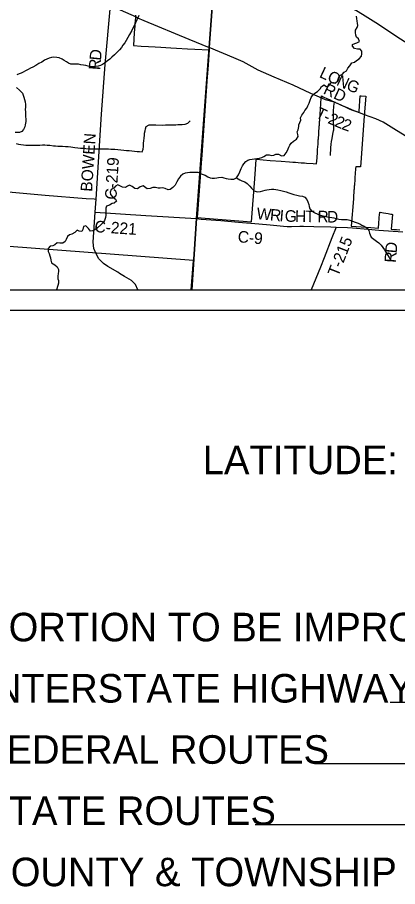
# Model space of a CAD drawing. Extents: x 0 to 34, y 0 to 22.
# Drawn here: x 2.162 to 4.027, y 11.175 to 15.435 of the extents above; entities that cross this region are included whole.
import ezdxf

# ---------------------------------------------------------------- set-up
doc = ezdxf.new("R2010")
doc.units = 0
for name, color, linetype in [('GM_X_Corporation', 7, 'Continuous'), ('GM_X_County', 7, 'Continuous'), ('GM_X_County_Road', 7, 'Continuous'), ('GM_X_County_Road_Text', 7, 'Continuous'), ('GM_X_Minor_River', 7, 'Continuous'), ('GM_X_Rail_Line', 7, 'Continuous'), ('GM_X_Township_Road', 7, 'Continuous'), ('GM_X_Township_Road_Text', 7, 'Continuous'), ('SH_Data', 7, 'Continuous'), ('SH_Text', 7, 'Continuous')]:
    doc.layers.add(name, color=color, linetype=linetype)

msp = doc.modelspace()

# ---------------------------------------------------------------- linework, layer by layer
at = {"layer": 'GM_X_Corporation'}
for points in [[(4.3071, 20.9), (2.1, 20.9), (2.1, 14.1), (3.0169, 14.1), (3.0406, 14.4484), (3.1026, 15.287), (3.1745, 16.2606), (2.934, 16.2765), (2.366, 16.3159), (2.2862, 16.3208), (2.1768, 16.323), (2.2478, 17.3472), (2.3155, 18.3567), (3.8153, 18.2543), (3.8503, 18.7566), (3.8611, 18.9124), (3.8924, 19.3621), (3.9019, 19.4987), (3.9133, 19.6628), (3.9816, 20.645), (3.9912, 20.7822), (4.2975, 20.7549)], [(2.1, 16.3272), (2.1, 14.1), (3.0167, 14.1), (3.0404, 14.449), (3.1023, 15.2875), (3.1743, 16.2612), (2.9338, 16.2771), (2.3658, 16.3164), (2.2859, 16.3213), (2.2263, 16.32), (2.2052, 16.32), (2.1768, 16.3213)], [(2.1, 14.3139), (2.1, 14.1), (3.0148, 14.1), (3.0256, 14.2426)]]:
    msp.add_lwpolyline(points, close=True, dxfattribs=at)
for points in [[(2.1, 20.9), (2.1, 14.1), (3.0167, 14.1), (3.0404, 14.449), (3.1023, 15.2875), (3.1743, 16.2612)], [(6.5646, 18.0583), (6.0906, 18.0978), (6.0343, 18.1015), (5.9465, 18.1082), (5.8371, 18.1158), (5.5447, 18.1318), (4.9551, 18.1768), (4.7449, 18.1929), (4.5528, 18.2021), (4.3271, 18.2226), (4.1999, 18.2271), (3.8153, 18.2543), (2.3155, 18.3567), (2.2478, 17.3472), (2.1768, 16.323), (2.2862, 16.3208), (2.366, 16.3159), (2.934, 16.2765), (3.1745, 16.2606), (3.1026, 15.287), (3.0406, 14.4484), (3.0169, 14.1), (8.9, 14.1)], [(3.1743, 16.2612), (3.1023, 15.2875), (3.0404, 14.449), (3.0167, 14.1), (8.9, 14.1)], [(3.1743, 16.2612), (3.1023, 15.2875), (3.0404, 14.449), (3.0167, 14.1), (8.1011, 14.1)], [(2.7417, 15.4453), (2.7408, 15.4323), (2.7387, 15.4036), (2.7379, 15.3931), (2.7354, 15.3598), (2.7307, 15.2967), (2.7691, 15.2945), (2.8046, 15.2924), (2.837, 15.2905), (2.866, 15.2888), (2.8901, 15.2874), (2.914, 15.286), (2.942, 15.2843), (2.9958, 15.2812), (3.0329, 15.279), (3.1028, 15.2753), (3.0975, 15.2023), (3.0918, 15.1226), (3.066, 14.7602), (3.0631, 14.72), (3.0452, 14.4739), (3.0438, 14.4548), (3.0831, 14.4515), (3.3102, 14.4323), (3.3258, 14.6436), (3.3329, 14.7391), (3.3329, 14.7394), (3.3334, 14.7393), (3.4016, 14.7339), (3.455, 14.7297), (3.4969, 14.7266), (3.5123, 14.7255), (3.5125, 14.7254), (3.5257, 14.7245), (3.539, 14.7235), (3.5533, 14.7224), (3.5632, 14.7217), (3.5697, 14.7212), (3.579, 14.7205), (3.613, 14.718), (3.6292, 14.7168), (3.6303, 14.7318), (3.6313, 14.7465), (3.6333, 14.7735), (3.6343, 14.7878), (3.6343, 14.788), (3.6362, 14.8135), (3.6364, 14.8164), (3.6378, 14.8363), (3.6379, 14.8368), (3.6384, 14.8447), (3.6395, 14.8596), (3.6405, 14.873), (3.6406, 14.8747), (3.6421, 14.8948), (3.6425, 14.9014), (3.6426, 14.9026), (3.6427, 14.9037), (3.6428, 14.9053), (3.6431, 14.9095), (3.6434, 14.9128), (3.6436, 14.9159), (3.6441, 14.9233), (3.6442, 14.9238), (3.6446, 14.9297), (3.6453, 14.94), (3.6466, 14.958), (3.6468, 14.9605), (3.6474, 14.9687), (3.6481, 14.9777), (3.6492, 14.9929), (3.6499, 15.0034), (3.6506, 15.0128), (3.6525, 15.0397), (3.6527, 15.042), (3.6528, 15.0438), (3.653, 15.0461), (3.6533, 15.0498), (3.6621, 15.0457), (3.682, 15.0363), (3.6918, 15.0318), (3.7108, 15.0228), (3.7125, 15.022), (3.7147, 15.021), (3.7197, 15.0187), (3.7217, 15.0178), (3.7338, 15.0123), (3.7512, 15.0044), (3.78, 14.9913), (3.789, 14.9872), (3.8003, 14.982), (3.8246, 14.9729), (3.8378, 14.968), (3.8383, 14.9758), (3.8437, 15.0498), (3.8478, 15.0496), (3.8706, 15.0481), (3.865, 14.9723), (3.8648, 14.9698), (3.8646, 14.9666), (3.864, 14.9589), (3.8634, 14.9507), (3.8466, 14.7235), (3.845, 14.7016), (3.8442, 14.7016), (3.8212, 14.7029), (3.8205, 14.6938), (3.8186, 14.6684), (3.8173, 14.6513), (3.8162, 14.6359), (3.815, 14.6195), (3.8145, 14.6129), (3.8141, 14.6075), (3.8136, 14.6023), (3.8129, 14.5912), (3.8127, 14.5895), (3.8117, 14.576), (3.8106, 14.5611), (3.8095, 14.5458), (3.7995, 14.4119), (3.8719, 14.4063), (3.8946, 14.4045), (3.9328, 14.4015), (3.9346, 14.4255), (3.9382, 14.4723), (3.9386, 14.4761), (3.9388, 14.4798), (3.9416, 14.4794), (3.9579, 14.4766), (3.9801, 14.4729), (3.9939, 14.4705), (3.9984, 14.4697), (4.0012, 14.4693), (3.9984, 14.4324), (3.9956, 14.3966), (4.008, 14.3957), (4.0204, 14.3947), (4.0371, 14.3934)]]:
    msp.add_lwpolyline(points, dxfattribs=at)
at = {"layer": 'GM_X_County'}
msp.add_lwpolyline([(3.0167, 14.1), (3.0404, 14.449), (3.1023, 15.2875), (3.1743, 16.2612)], dxfattribs=at)
at = {"layer": 'GM_X_County_Road'}
for p in [(2.5381, 14.5448), (2.5442, 14.4799)]:
    msp.add_line(p, (2.5479, 14.5441), dxfattribs=at)
for points in [[(2.5479, 14.5441), (2.5748, 14.9604), (2.5921, 15.2034), (2.6186, 15.4932)], [(2.6094, 15.4971), (2.6186, 15.4932), (2.6658, 15.4721), (2.7439, 15.4371), (2.7518, 15.4334)], [(2.7518, 15.4334), (2.7817, 15.4197), (3.0028, 15.3278), (3.1026, 15.287)], [(2.1, 14.5816), (2.1002, 14.5816), (2.2989, 14.564), (2.4998, 14.5475), (2.5381, 14.5448)], [(2.6542, 14.1854), (2.6063, 14.2143), (2.5847, 14.2288), (2.5612, 14.2519), (2.5476, 14.2754), (2.537, 14.3018), (2.5334, 14.3332), (2.5442, 14.4799)], [(2.5442, 14.4799), (2.7924, 14.4639), (3.0406, 14.4484)], [(3.0406, 14.4484), (3.0634, 14.4466), (3.1595, 14.4386), (3.2462, 14.4312), (3.3454, 14.4224), (3.4012, 14.4174), (3.4662, 14.4115), (3.4849, 14.4106), (3.5067, 14.4104), (3.5471, 14.4112), (3.5658, 14.4113), (3.6155, 14.41), (3.6993, 14.4076), (3.7246, 14.4066), (3.7801, 14.4043), (3.805, 14.403), (3.8823, 14.3972), (3.9351, 14.3926), (4.0515, 14.3841)], [(2.728, 14.1381), (2.7213, 14.145), (2.6875, 14.1654), (2.6633, 14.18), (2.6542, 14.1854)], [(2.752, 14.1), (2.7406, 14.1249), (2.728, 14.1381)]]:
    msp.add_lwpolyline(points, dxfattribs=at)
at = {"layer": 'GM_X_Minor_River'}
for points in [[(2.7571, 15.4447), (2.7529, 15.4333), (2.7483, 15.4231), (2.7418, 15.4087), (2.736, 15.3966), (2.7295, 15.3845), (2.7226, 15.3709), (2.7119, 15.3512), (2.7039, 15.3357), (2.6959, 15.3217), (2.6882, 15.31), (2.6798, 15.2983), (2.6722, 15.2873), (2.6634, 15.2764), (2.6516, 15.2639), (2.6387, 15.2511), (2.6254, 15.2394), (2.6148, 15.2307), (2.6034, 15.2225), (2.5897, 15.2108), (2.5802, 15.2044), (2.5692, 15.1992), (2.5582, 15.1958), (2.5434, 15.1936), (2.5332, 15.1929), (2.5204, 15.1922), (2.5098, 15.1954), (2.4973, 15.1985), (2.4864, 15.2), (2.4732, 15.2024), (2.4618, 15.2048), (2.4505, 15.2056), (2.4388, 15.2053), (2.424, 15.2061), (2.4127, 15.2108), (2.4021, 15.2169), (2.392, 15.223), (2.381, 15.2295), (2.3675, 15.2361), (2.3558, 15.2384), (2.3406, 15.2397), (2.3297, 15.2386), (2.3172, 15.2349), (2.3062, 15.23), (2.2948, 15.2251), (2.2815, 15.2161), (2.2671, 15.2082), (2.2519, 15.1988), (2.2375, 15.1906), (2.2261, 15.1853), (2.2147, 15.179), (2.2022, 15.173), (2.1904, 15.167), (2.1806, 15.1621), (2.1707, 15.1584)], [(3.8195, 15.361), (3.8208, 15.372), (3.8277, 15.3848), (3.832, 15.3946), (3.8303, 15.4064), (3.8286, 15.4159), (3.8265, 15.4292), (3.8244, 15.441)], [(3.0573, 14.6718), (3.058, 14.6698), (3.0682, 14.6666), (3.0821, 14.6611), (3.0964, 14.6533), (3.1077, 14.6478), (3.1179, 14.6465), (3.1281, 14.6472), (3.1395, 14.6481), (3.149, 14.6499), (3.1645, 14.652), (3.1751, 14.6488), (3.1852, 14.6452), (3.1962, 14.6432), (3.209, 14.6419), (3.223, 14.6424), (3.2371, 14.6483), (3.2457, 14.6634), (3.253, 14.6777), (3.2593, 14.6939), (3.2663, 14.7075), (3.2722, 14.7173), (3.2829, 14.7281), (3.2928, 14.7348), (3.3024, 14.7385), (3.3126, 14.7399), (3.3247, 14.7412), (3.3361, 14.743), (3.3494, 14.7454), (3.36, 14.7479), (3.3707, 14.7535), (3.3833, 14.7605), (3.3962, 14.7619), (3.4078, 14.7583), (3.4196, 14.7593), (3.4291, 14.7648), (3.4431, 14.7643), (3.4566, 14.7569), (3.4695, 14.7586), (3.4795, 14.771), (3.4865, 14.7822), (3.4932, 14.7981), (3.4986, 14.8083), (3.5052, 14.8188), (3.5167, 14.8274), (3.5308, 14.8382), (3.5382, 14.851), (3.5372, 14.8609), (3.5344, 14.8738), (3.5383, 14.8836), (3.5423, 14.8995), (3.5421, 14.909), (3.5464, 14.9192), (3.5518, 14.9313), (3.5505, 14.943), (3.5575, 14.9562), (3.566, 14.9686), (3.5718, 14.9784), (3.5814, 14.9904), (3.5869, 15.001), (3.5928, 15.0149), (3.5986, 15.0293), (3.6034, 15.0414), (3.6092, 15.0527), (3.6211, 15.0639), (3.6333, 15.0713), (3.6464, 15.084), (3.6541, 15.0968), (3.6671, 15.1035), (3.6768, 15.0965), (3.6897, 15.0998), (3.6994, 15.1141), (3.7127, 15.1158), (3.7224, 15.1118), (3.7313, 15.1223), (3.7372, 15.1367), (3.7415, 15.1503), (3.7541, 15.1543), (3.7637, 15.1663), (3.7767, 15.173), (3.7825, 15.1862), (3.7918, 15.1978), (3.8026, 15.2113), (3.8151, 15.2157), (3.8255, 15.2239), (3.8388, 15.2321), (3.8492, 15.2452), (3.8513, 15.2558), (3.8515, 15.2698), (3.8425, 15.2798), (3.83, 15.2785), (3.8157, 15.2821), (3.8056, 15.2932), (3.8058, 15.3027), (3.8176, 15.3075), (3.8271, 15.31), (3.8389, 15.3163), (3.8353, 15.3293), (3.8252, 15.3378), (3.8215, 15.3473), (3.8195, 15.361)], [(2.1707, 15.1584), (2.1601, 15.1535)], [(2.1575, 15.0905), (2.1721, 15.0775), (2.1864, 15.0634), (2.1909, 15.0535), (2.1942, 15.0436), (2.1972, 15.0322), (2.1994, 15.0208), (2.2012, 15.0087), (2.2015, 14.9954), (2.2007, 14.984), (2.2013, 14.9719), (2.2017, 14.962), (2.2023, 14.9479), (2.203, 14.9381), (2.2029, 14.924), (2.201, 14.9089), (2.1983, 14.899), (2.1921, 14.8858), (2.1845, 14.876), (2.172, 14.8707), (2.1519, 14.8708)], [(2.1561, 14.8162), (2.1678, 14.8131), (2.1792, 14.8122), (2.1928, 14.8103), (2.203, 14.8091), (2.2211, 14.8082), (2.2344, 14.8081), (2.2499, 14.8084), (2.2612, 14.8087), (2.2722, 14.809), (2.2854, 14.8097), (2.2972, 14.8096), (2.3089, 14.8084), (2.3213, 14.8079), (2.3384, 14.8059), (2.3489, 14.8051), (2.361, 14.8043), (2.3716, 14.8034), (2.3841, 14.803), (2.3985, 14.8025), (2.4106, 14.8013), (2.4245, 14.7997), (2.4442, 14.7973), (2.4589, 14.7957), (2.4714, 14.7945), (2.4861, 14.794), (2.4982, 14.7924), (2.5115, 14.7908), (2.5236, 14.79), (2.5349, 14.7903), (2.5462, 14.7902), (2.5591, 14.7913), (2.5705, 14.7908), (2.595, 14.7907), (2.6086, 14.7902), (2.6196, 14.7894), (2.6298, 14.7889), (2.6396, 14.7885), (2.6544, 14.7877), (2.6687, 14.7864), (2.6842, 14.7848), (2.6971, 14.7828), (2.7099, 14.782), (2.7235, 14.7812), (2.7368, 14.7796), (2.7492, 14.778), (2.7606, 14.7768), (2.7742, 14.7759), (2.7784, 14.7895), (2.78, 14.8017), (2.7813, 14.818), (2.7821, 14.8305), (2.7837, 14.8434), (2.7849, 14.8578), (2.7861, 14.8677), (2.788, 14.8783), (2.7896, 14.8885), (2.7935, 14.9006), (2.8083, 14.9081), (2.8196, 14.9088), (2.8302, 14.908), (2.8404, 14.9076), (2.8756, 14.9073), (2.8881, 14.908), (2.9115, 14.9079), (2.9255, 14.9082), (2.9384, 14.9088), (2.9486, 14.9092), (2.9592, 14.9099), (2.9701, 14.9105), (2.9841, 14.9112), (2.9974, 14.9161), (3.0096, 14.9278)], [(3.0573, 14.6718), (3.0485, 14.6744), (3.0383, 14.6745), (3.0284, 14.6749), (3.0182, 14.6754), (3.0069, 14.6754), (2.9963, 14.6736), (2.9846, 14.6718), (2.9732, 14.6665), (2.9622, 14.6571), (2.9515, 14.6431), (2.9434, 14.6284), (2.9354, 14.6125), (2.9236, 14.6008), (2.9111, 14.5914), (2.9012, 14.5903), (2.8869, 14.5965), (2.8737, 14.6), (2.862, 14.5978), (2.8521, 14.5986), (2.8389, 14.6009), (2.8257, 14.6006), (2.8124, 14.5966), (2.7992, 14.5944), (2.7781, 14.6097), (2.7644, 14.6048), (2.7504, 14.5939), (2.7379, 14.5959), (2.7244, 14.6066), (2.7123, 14.6124), (2.7024, 14.6082), (2.6922, 14.6019), (2.6778, 14.6031), (2.6676, 14.6077), (2.6552, 14.6138), (2.6427, 14.6071), (2.6351, 14.5973), (2.6218, 14.5909), (2.6164, 14.5777), (2.6186, 14.5666), (2.6306, 14.554), (2.6427, 14.5433), (2.6483, 14.5334), (2.6373, 14.524), (2.627, 14.5226), (2.6137, 14.5143), (2.5997, 14.5102), (2.5959, 14.5004), (2.5962, 14.4859), (2.5957, 14.4746), (2.5953, 14.4647), (2.5948, 14.4533), (2.5898, 14.4401), (2.5818, 14.4284), (2.5716, 14.4182), (2.5544, 14.4031), (2.5412, 14.3937), (2.5305, 14.3881), (2.5207, 14.3878), (2.5102, 14.4007), (2.4985, 14.4129), (2.486, 14.4092), (2.4822, 14.3952), (2.4783, 14.3854), (2.4655, 14.3877), (2.4553, 14.3927), (2.4443, 14.3799), (2.4298, 14.3716), (2.4181, 14.369), (2.4086, 14.3608), (2.4017, 14.3468), (2.3956, 14.3365), (2.3853, 14.3283), (2.371, 14.3276), (2.3577, 14.3296), (2.346, 14.3209), (2.3361, 14.3149), (2.3232, 14.3139), (2.3129, 14.3021), (2.3129, 14.2877), (2.3173, 14.2775), (2.3218, 14.2657), (2.3248, 14.2562), (2.3262, 14.2444), (2.3299, 14.2318), (2.3453, 14.2215), (2.3566, 14.2123), (2.3634, 14.1994), (2.3637, 14.1895), (2.3617, 14.18), (2.3598, 14.1671), (2.3608, 14.1542), (2.363, 14.1447), (2.3633, 14.133), (2.3606, 14.1201), (2.354, 14.1)], [(3.2371, 14.6483), (3.2525, 14.639), (3.2634, 14.6335), (3.2769, 14.6284), (3.2882, 14.6214), (3.302, 14.6072), (3.3109, 14.5972), (3.3229, 14.5853), (3.3376, 14.5794), (3.3542, 14.5814), (3.3653, 14.5851), (3.3767, 14.5879), (3.3861, 14.5897), (3.3964, 14.5915), (3.4089, 14.5928), (3.4203, 14.5934), (3.4399, 14.5901), (3.4542, 14.5869), (3.467, 14.5836), (3.4795, 14.5804), (3.493, 14.5753), (3.5179, 14.5674), (3.5322, 14.5634), (3.5458, 14.5609), (3.5609, 14.5584), (3.5711, 14.5545), (3.5811, 14.5426), (3.5862, 14.5304), (3.5906, 14.5178), (3.5927, 14.5075), (3.596, 14.4972), (3.606, 14.4846), (3.6199, 14.4772), (3.632, 14.4713), (3.6425, 14.467), (3.6549, 14.4634), (3.6677, 14.4598), (3.6828, 14.4569), (3.693, 14.4557), (3.7036, 14.4544), (3.7146, 14.4523), (3.7251, 14.4491), (3.7383, 14.4459), (3.7515, 14.445), (3.7671, 14.4448), (3.7799, 14.4435), (3.7916, 14.441), (3.8052, 14.4367), (3.8187, 14.4319), (3.8289, 14.428), (3.8409, 14.4225), (3.8514, 14.417), (3.8631, 14.4108), (3.8773, 14.4019), (3.8847, 14.3904), (3.8887, 14.3778), (3.8912, 14.3683), (3.8975, 14.3572), (3.9106, 14.3475), (3.9233, 14.3379), (3.9338, 14.3294), (3.9465, 14.3178), (3.9547, 14.3071), (3.9617, 14.2956), (3.9688, 14.2845), (3.9765, 14.2715), (3.9847, 14.2585), (3.9924, 14.247)]]:
    msp.add_lwpolyline(points, dxfattribs=at)
at = {"layer": 'GM_X_Rail_Line'}
msp.add_lwpolyline([(5.9528, 14.1), (5.6437, 14.2982), (5.4789, 14.4041), (4.8128, 14.8326), (4.5194, 15.0215), (4.222, 15.2127), (4.0411, 15.3289), (3.919, 15.4076), (3.8544, 15.4493), (3.8245, 15.4671), (3.7478, 15.5086), (3.3032, 15.7468), (3.1426, 15.8323)], dxfattribs=at)
at = {"layer": 'GM_X_Township_Road'}
for points in [[(3.6434, 15.0432), (3.6013, 15.0623), (3.5146, 15.102), (3.4207, 15.1424), (3.342, 15.1763), (3.2696, 15.2174), (3.2241, 15.2359), (3.1026, 15.287)], [(3.8367, 14.9683), (3.8059, 14.9802), (3.7801, 14.9909), (3.7518, 15.0033), (3.7165, 15.0193), (3.6725, 15.03), (3.6434, 15.0432)], [(3.697, 14.7573), (3.6993, 14.7957), (3.7008, 14.8142), (3.7023, 14.8265), (3.7049, 14.8417), (3.7093, 14.863), (3.7123, 14.8782), (3.7132, 14.8844), (3.7139, 14.8938), (3.7139, 14.9032), (3.7129, 14.9187), (3.7118, 14.9372), (3.7117, 14.9558), (3.7124, 14.9744), (3.7142, 14.9991), (3.7165, 15.0193)], [(3.8647, 14.9575), (3.8638, 14.9578), (3.8367, 14.9683)], [(4.0854, 14.8414), (4.0084, 14.8887), (3.9551, 14.9218), (3.9202, 14.9373), (3.8647, 14.9575)], [(3.7246, 14.4066), (3.7046, 14.3546), (3.6661, 14.2563), (3.6481, 14.21), (3.6149, 14.1273), (3.6029, 14.1)]]:
    msp.add_lwpolyline(points, dxfattribs=at)
at = {"layer": 'SH_Data'}
for p, q in [((2.1, 14.1), (8.9, 14.1)), ((2, 14), (9, 14)), ((7.7, 12.0767), (3.9895, 12.0767)), ((7.7, 11.7767), (3.6192, 11.7767)), ((7.7, 11.4767), (3.3288, 11.4767))]:
    msp.add_line(p, q, dxfattribs=at)

# ---------------------------------------------------------------- texts
at = {"layer": 'GM_X_County_Road_Text'}
for s, height, rotation, p in [('D', 0.0568, 84.4652, (2.5717, 15.2216)), ('R', 0.0568, 85.7692, (2.5683, 15.1754)), ('BOWEN', 0.05682, 86.2604, (2.5283, 14.5792)), ('C-219', 0.05682, 86.4074, (2.6475, 14.5407)), ('W', 0.0568, 354.7109, (3.3332, 14.4463)), ('R', 0.0568, 354.7364, (3.3988, 14.4402)), ('I', 0.0568, 355.0852, (3.4457, 14.4359)), ('G', 0.0568, 358.5756, (3.4727, 14.4337)), ('H', 0.0568, 359.0437, (3.5232, 14.4325)), ('T', 0.0568, 359.0459, (3.5732, 14.4316)), ('R', 0.0568, 359.0455, (3.6332, 14.4306)), ('D', 0.0568, 359.0455, (3.6798, 14.4298)), ('C-221', 0.05682, 356.1494, (2.539, 14.3825)), ('C-9', 0.05682, 354.9719, (3.2408, 14.3332))]:
    msp.add_text(s, height=height, rotation=rotation, dxfattribs=at).set_placement(p)
at = {"layer": 'GM_X_Township_Road_Text'}
for s, height, rotation, p in [('L', 0.0568, 335.0058, (3.6389, 15.1436)), ('O', 0.0568, 335.0007, (3.6774, 15.1256)), ('N', 0.0568, 335.058, (3.7228, 15.1044)), ('G', 0.0568, 338.2778, (3.7713, 15.082)), ('RD', 0.05682, 334.9831, (3.6581, 15.063)), ('T', 0.0568, 334.8821, (3.62, 14.9464)), ('2', 0.0568, 335.6564, (3.6804, 14.9182)), ('-', 0.0568, 335.0508, (3.6587, 14.9283)), ('2', 0.0568, 336.928, (3.7136, 14.9032)), ('2', 0.0568, 339.6753, (3.7485, 14.8884)), ('T-215', 0.05682, 68.5613, (3.7345, 14.1612)), ('D', 0.0568, 84.9263, (4.0216, 14.2773)), ('R', 0.0568, 86.3092, (4.0186, 14.2311))]:
    msp.add_text(s, height=height, rotation=rotation, dxfattribs=at).set_placement(p)
at = {"layer": 'SH_Text'}
for s, p in [('LATITUDE:  39°55\'49"     LONGITUDE:  -82°44\'43"', (3.071, 13.1959)), ('PORTION TO BE IMPROVED', (1.9944, 12.3767)), ('INTERSTATE HIGHWAY', (1.9944, 12.0767)), ('FEDERAL ROUTES', (1.9944, 11.7767)), ('STATE ROUTES', (1.9944, 11.4767)), ('COUNTY & TOWNSHIP ROADS', (1.9944, 11.1767))]:
    msp.add_text(s, height=0.14, dxfattribs=at).set_placement(p)

doc.saveas('drawing.dxf')
